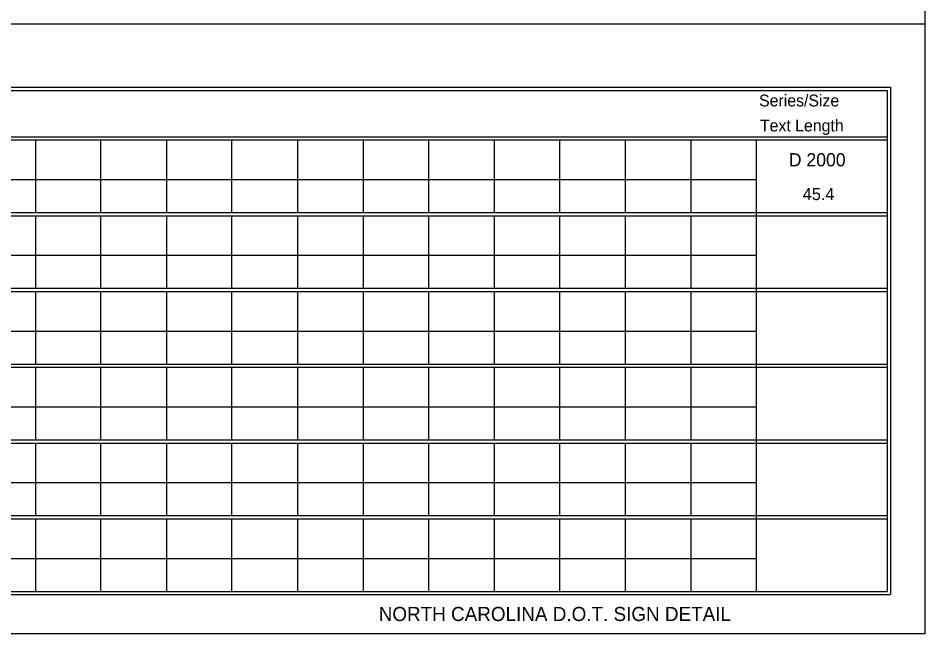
# Model space of a CAD drawing. Extents: x 768137 to 769825, y 651421 to 652521.
# Drawn here: x 769087.4 to 769457, y 651713.3 to 651964.1 of the extents above; entities that cross this region are included whole.
import ezdxf

# ---------------------------------------------------------------- set-up
doc = ezdxf.new("R2010")
doc.units = 0
doc.layers.add('Text', color=7, linetype='Continuous')

msp = doc.modelspace()

# ---------------------------------------------------------------- linework, layer by layer
at = {"layer": 'Text'}
for p, q in [((768955.49, 651961.74), (769456.98, 651961.74)), ((768639.96, 651915.79), (769276.27, 651915.79)), ((768639.96, 651914.45), (769276.27, 651914.45)), ((769094.43, 651914.45), (769094.43, 651884.92)), ((769120.99, 651914.45), (769120.99, 651884.92)), ((769147.82, 651914.45), (769147.82, 651884.92)), ((769174.37, 651914.45), (769174.37, 651884.92)), ((769201.2, 651914.45), (769201.2, 651884.92)), ((769228.03, 651914.45), (769228.03, 651884.92)), ((769247.8, 651915.79), (769441.58, 651915.79)), ((769247.8, 651914.45), (769441.58, 651914.45)), ((769254.59, 651914.45), (769254.59, 651884.92)), ((769254.59, 651914.45), (769254.59, 651884.92)), ((769281.42, 651914.45), (769281.42, 651884.92)), ((769307.98, 651914.45), (769307.98, 651884.92)), ((769334.81, 651914.45), (769334.81, 651884.92)), ((769361.64, 651914.45), (769361.64, 651884.92)), ((769388.19, 651914.45), (769388.19, 651735.51)), ((768666.79, 651898.34), (769276.27, 651898.34)), ((769247.8, 651898.34), (769388.19, 651898.34)), ((769388.19, 651892.22), (769388.19, 651884.92)), ((768639.96, 651884.92), (769276.27, 651884.92)), ((769247.8, 651884.92), (769441.58, 651884.92)), ((768639.96, 651883.58), (769276.27, 651883.58)), ((769094.43, 651883.58), (769094.43, 651854.06)), ((769120.99, 651883.58), (769120.99, 651854.06)), ((769147.82, 651883.58), (769147.82, 651854.06)), ((769174.37, 651883.58), (769174.37, 651854.06)), ((769201.2, 651883.58), (769201.2, 651854.06)), ((769228.03, 651883.58), (769228.03, 651854.06)), ((769247.8, 651883.58), (769441.58, 651883.58)), ((769254.59, 651883.58), (769254.59, 651854.06)), ((769254.59, 651883.58), (769254.59, 651854.06)), ((769281.42, 651883.58), (769281.42, 651854.06)), ((769307.98, 651883.58), (769307.98, 651854.06)), ((769334.81, 651883.58), (769334.81, 651854.06)), ((769361.64, 651883.58), (769361.64, 651854.06)), ((769388.19, 651883.58), (769388.19, 651869.57)), ((768666.79, 651867.48), (769276.27, 651867.48)), ((769247.8, 651867.48), (769388.19, 651867.48)), ((769388.19, 651863.67), (769388.19, 651854.06)), ((768639.96, 651854.06), (769276.27, 651854.06)), ((768639.96, 651852.72), (769276.27, 651852.72)), ((769094.43, 651852.72), (769094.43, 651823.19)), ((769120.99, 651852.72), (769120.99, 651823.19)), ((769147.82, 651852.72), (769147.82, 651823.19)), ((769174.37, 651852.72), (769174.37, 651823.19)), ((769201.2, 651852.72), (769201.2, 651823.19)), ((769228.03, 651852.72), (769228.03, 651823.19)), ((769247.8, 651854.06), (769441.58, 651854.06)), ((769247.8, 651852.72), (769441.58, 651852.72)), ((769254.59, 651852.72), (769254.59, 651823.19)), ((769254.59, 651852.72), (769254.59, 651823.19)), ((769281.42, 651852.72), (769281.42, 651823.19)), ((769307.98, 651852.72), (769307.98, 651823.19)), ((769334.81, 651852.72), (769334.81, 651823.19)), ((769361.64, 651852.72), (769361.64, 651823.19)), ((769388.19, 651852.72), (769388.19, 651840.72)), ((768666.79, 651836.61), (769276.27, 651836.61)), ((769247.8, 651836.61), (769388.19, 651836.61)), ((769388.19, 651831.89), (769388.19, 651823.19)), ((768639.96, 651823.19), (769276.27, 651823.19)), ((768639.96, 651821.85), (769276.27, 651821.85)), ((769094.43, 651821.85), (769094.43, 651792.32)), ((769120.99, 651821.85), (769120.99, 651792.32)), ((769147.82, 651821.85), (769147.82, 651792.32)), ((769174.37, 651821.85), (769174.37, 651792.32)), ((769201.2, 651821.85), (769201.2, 651792.32)), ((769228.03, 651821.85), (769228.03, 651792.32)), ((769247.8, 651823.19), (769441.58, 651823.19)), ((769247.8, 651821.85), (769441.58, 651821.85)), ((769254.59, 651821.85), (769254.59, 651792.32)), ((769254.59, 651821.85), (769254.59, 651792.32)), ((769281.42, 651821.85), (769281.42, 651792.32)), ((769307.98, 651821.85), (769307.98, 651792.32)), ((769334.81, 651821.85), (769334.81, 651792.32)), ((769361.64, 651821.85), (769361.64, 651792.32)), ((769388.19, 651821.85), (769388.19, 651808.91)), ((768666.79, 651805.74), (769276.27, 651805.74)), ((769247.8, 651805.74), (769388.19, 651805.74)), ((769388.19, 651800.08), (769388.19, 651792.32)), ((769094.43, 651795.76), (769094.43, 651792.32)), ((769120.99, 651795.76), (769120.99, 651792.32)), ((769147.82, 651795.76), (769147.82, 651792.32)), ((769174.37, 651795.76), (769174.37, 651792.32)), ((769201.2, 651795.76), (769201.2, 651792.32)), ((769228.03, 651795.76), (769228.03, 651792.32)), ((769254.59, 651795.76), (769254.59, 651792.32)), ((769254.59, 651795.76), (769254.59, 651792.32)), ((769281.42, 651795.76), (769281.42, 651792.32)), ((769307.98, 651795.76), (769307.98, 651792.32)), ((769334.81, 651795.76), (769334.81, 651792.32)), ((769361.64, 651795.76), (769361.64, 651792.32)), ((769388.19, 651795.76), (769388.19, 651792.32)), ((768639.96, 651792.32), (769276.27, 651792.32)), ((768639.96, 651792.32), (769276.27, 651792.32)), ((769247.8, 651792.32), (769441.58, 651792.32)), ((769247.8, 651792.32), (769441.58, 651792.32)), ((768639.96, 651790.98), (769276.27, 651790.98)), ((768639.96, 651790.98), (769276.27, 651790.98)), ((769094.43, 651790.98), (769094.43, 651763.39)), ((769094.43, 651790.98), (769094.43, 651761.46)), ((769120.99, 651790.98), (769120.99, 651763.39)), ((769120.99, 651790.98), (769120.99, 651761.46)), ((769147.82, 651790.98), (769147.82, 651763.39)), ((769147.82, 651790.98), (769147.82, 651761.46)), ((769174.37, 651790.98), (769174.37, 651763.39)), ((769174.37, 651790.98), (769174.37, 651761.46)), ((769201.2, 651790.98), (769201.2, 651763.39)), ((769201.2, 651790.98), (769201.2, 651761.46)), ((769228.03, 651790.98), (769228.03, 651763.39)), ((769228.03, 651790.98), (769228.03, 651761.46)), ((769247.8, 651790.98), (769441.58, 651790.98)), ((769247.8, 651790.98), (769441.58, 651790.98)), ((769254.59, 651790.98), (769254.59, 651763.39)), ((769254.59, 651790.98), (769254.59, 651761.46)), ((769254.59, 651790.98), (769254.59, 651763.39)), ((769254.59, 651790.98), (769254.59, 651761.46)), ((769281.42, 651790.98), (769281.42, 651763.39)), ((769281.42, 651790.98), (769281.42, 651761.46)), ((769307.98, 651790.98), (769307.98, 651763.39)), ((769307.98, 651790.98), (769307.98, 651761.46)), ((769334.81, 651790.98), (769334.81, 651763.39)), ((769334.81, 651790.98), (769334.81, 651761.46)), ((769361.64, 651790.98), (769361.64, 651763.39)), ((769361.64, 651790.98), (769361.64, 651761.46)), ((769388.19, 651790.98), (769388.19, 651777.7)), ((769388.19, 651790.98), (769388.19, 651777.7)), ((768666.79, 651774.88), (769276.27, 651774.88)), ((768666.79, 651774.88), (769276.27, 651774.88)), ((769247.8, 651774.88), (769388.19, 651774.88)), ((769247.8, 651774.88), (769381.24, 651774.88)), ((769388.19, 651770.05), (769388.19, 651763.39)), ((769388.19, 651770.05), (769388.19, 651761.46)), ((769094.43, 651764.89), (769094.43, 651761.46)), ((769120.99, 651764.89), (769120.99, 651761.46)), ((769147.82, 651764.89), (769147.82, 651761.46)), ((769174.37, 651764.89), (769174.37, 651761.46)), ((769201.2, 651764.89), (769201.2, 651761.46)), ((769228.03, 651764.89), (769228.03, 651761.46)), ((769254.59, 651764.89), (769254.59, 651761.46)), ((769254.59, 651764.89), (769254.59, 651761.46)), ((769281.42, 651764.89), (769281.42, 651761.46)), ((769307.98, 651764.89), (769307.98, 651761.46)), ((769334.81, 651764.89), (769334.81, 651761.46)), ((769361.64, 651764.89), (769361.64, 651761.46)), ((769388.19, 651764.89), (769388.19, 651761.46)), ((768639.96, 651761.46), (769276.27, 651761.46)), ((768639.96, 651761.46), (769276.27, 651761.46)), ((768639.96, 651760.11), (769276.27, 651760.11)), ((768639.96, 651760.11), (769276.27, 651760.11)), ((769094.43, 651760.11), (769094.43, 651730.59)), ((769094.43, 651760.11), (769094.43, 651730.59)), ((769120.99, 651760.11), (769120.99, 651730.59)), ((769120.99, 651760.11), (769120.99, 651730.59)), ((769147.82, 651760.11), (769147.82, 651730.59)), ((769147.82, 651760.11), (769147.82, 651730.59)), ((769174.37, 651760.11), (769174.37, 651730.59)), ((769174.37, 651760.11), (769174.37, 651730.59)), ((769201.2, 651760.11), (769201.2, 651730.59)), ((769201.2, 651760.11), (769201.2, 651730.59)), ((769228.03, 651760.11), (769228.03, 651730.59)), ((769228.03, 651760.11), (769228.03, 651730.59)), ((769247.8, 651761.46), (769441.58, 651761.46)), ((769247.8, 651761.46), (769441.58, 651761.46)), ((769247.8, 651760.11), (769441.58, 651760.11)), ((769247.8, 651760.11), (769441.58, 651760.11)), ((769254.59, 651760.11), (769254.59, 651730.59)), ((769254.59, 651760.11), (769254.59, 651730.59)), ((769254.59, 651760.11), (769254.59, 651730.59)), ((769254.59, 651760.11), (769254.59, 651730.59)), ((769281.42, 651760.11), (769281.42, 651730.59)), ((769281.42, 651760.11), (769281.42, 651730.59)), ((769307.98, 651760.11), (769307.98, 651730.59)), ((769307.98, 651760.11), (769307.98, 651730.59)), ((769334.81, 651760.11), (769334.81, 651730.59)), ((769334.81, 651760.11), (769334.81, 651730.59)), ((769361.64, 651760.11), (769361.64, 651730.59)), ((769361.64, 651760.11), (769361.64, 651730.59)), ((769388.19, 651760.11), (769388.19, 651747.69)), ((769388.19, 651760.11), (769388.19, 651747.69)), ((768666.79, 651744.01), (769276.27, 651744.01)), ((768666.79, 651744.01), (769276.27, 651744.01)), ((769247.8, 651744.01), (769388.19, 651744.01)), ((769247.8, 651744.01), (769383.05, 651744.01)), ((769388.19, 651738.27), (769388.19, 651730.59)), ((769388.19, 651738.27), (769388.19, 651730.59)), ((768638.59, 651729.25), (769276.27, 651729.25)), ((768639.96, 651730.59), (769276.27, 651730.59)), ((768639.96, 651730.59), (769276.27, 651730.59)), ((768639.96, 651729.25), (769276.27, 651729.25)), ((769247.8, 651730.59), (769441.58, 651730.59)), ((769247.8, 651730.59), (769441.58, 651730.59)), ((769247.8, 651729.25), (769442.95, 651729.25)), ((769247.8, 651729.25), (769441.58, 651729.25))]:
    msp.add_line(p, q, dxfattribs=at)
msp.add_lwpolyline([(768629.35, 652287.25), (769456.98, 652287.25), (769456.98, 651713.27), (768629.35, 651713.27)], close=True, dxfattribs=at)
for points in [[(768638.59, 651763.39), (768638.59, 651935.92), (769276.27, 651935.92)], [(768639.96, 651763.39), (768639.96, 651934.58), (769276.27, 651934.58)], [(769247.8, 651935.92), (769442.95, 651935.92), (769442.95, 651763.39)], [(769247.8, 651934.58), (769441.58, 651934.58), (769441.58, 651763.39)], [(769441.58, 651795.76), (769441.58, 651730.59)], [(769442.95, 651795.76), (769442.95, 651729.25)]]:
    msp.add_lwpolyline(points, dxfattribs=at)

# ---------------------------------------------------------------- texts
for s, height, p in [('Series/Size', 4.8313, (769389.4, 651928.11)), ('Text Length', 4.8313, (769389.75, 651917.94)), ('NORTH CAROLINA D.O.T. SIGN DETAIL', 5.7516, (769234.35, 651718.49))]:
    msp.add_text(s, height=height, rotation=360, dxfattribs=at).set_placement(p)
for s, height, p in [('D 2000', 5.368, (769401.53, 651903.71)), ('45.4', 4.96, (769407.2, 651889.95))]:
    msp.add_text(s, height=height, dxfattribs=at).set_placement(p)

doc.saveas('drawing.dxf')
